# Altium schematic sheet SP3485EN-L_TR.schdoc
size 127 x 101 mm
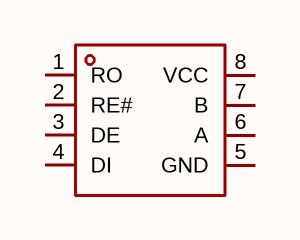
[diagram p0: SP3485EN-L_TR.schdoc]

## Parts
U?  sp3485en-l/tr  [SOIC-8_L5.0-W4.0-P1.27-LS6.0-BL]  (value not drawn)

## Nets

Not connected (* = marked no-connect by the designer): U? 1(RO) 2(RE#) 3(DE) 4(DI) 5(GND) 6(A) 7(B) 8(VCC)

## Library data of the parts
U? = sp3485en-l/tr: 类型:收发器;数据速率:10Mbps;; Manufacturer: MaxLinear(迈凌); AddInBom: yes; ModelId: 7abc64c95a1a4a04a4ef38f9097c870b; ModelTransform: 192.913,236.22,0,0,0,0,0,0,0; Number of Drivers: 1; Voltage - Supply: 3.3V; Data Rate: 10Mbps; Number of Nodes: 32; Quiescent Supply Current: 2mA; Communication Mode: 半双工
